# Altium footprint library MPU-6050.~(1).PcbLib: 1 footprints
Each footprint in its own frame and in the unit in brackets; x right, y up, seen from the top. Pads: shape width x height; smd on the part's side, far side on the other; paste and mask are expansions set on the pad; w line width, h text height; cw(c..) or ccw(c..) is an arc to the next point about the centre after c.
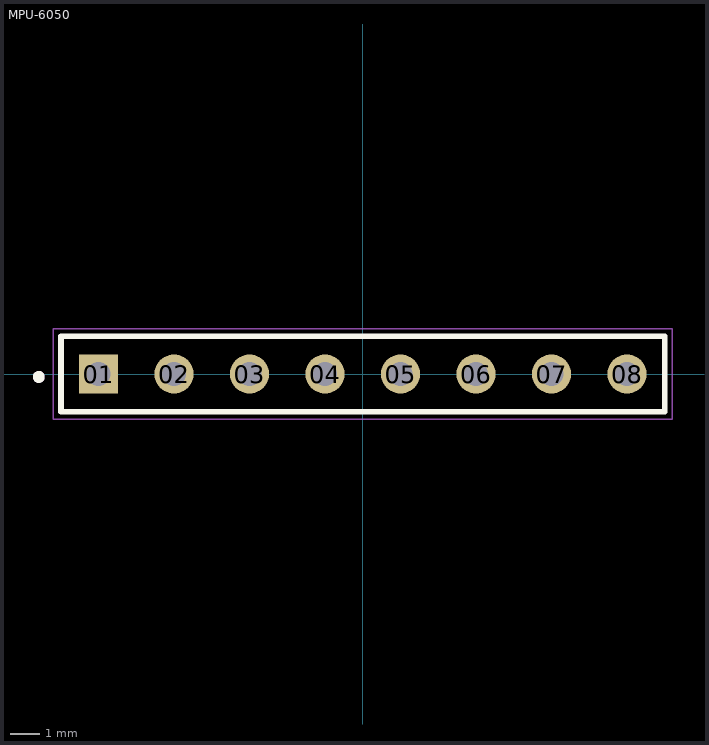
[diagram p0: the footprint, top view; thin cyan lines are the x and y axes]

## MPU-6050 [mil]
pads (8):
  rect 52x52 hole 32: 01(-350,0)
  round 52 hole 32: 02(-250,0) 03(-150,0) 04(-50,0) 05(50,0) 06(150,0) 07(250,0) 08(350,0)
Top Overlay:
  circle w7.87: c-429.13,-3.94 r3.94
  lines w7.87: -400,-50 -400,50 400,50 400,-50 -400,-50
Mechanical 13:
  circle w7.87: c-429.13,-3.94 r3.94
  lines w3.94: -400,-50 400,-50 400,50 -400,50 -400,-50
Mechanical 15:
  lines w1.97: -409.84,-59.84 409.84,-59.84 409.84,59.84 -409.84,59.84 -409.84,-59.84
3D body "MPU6050 With Mounting Hardware.step": height 61.69, standoff -640.43, extent -401.16,-45 401.16,555.39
